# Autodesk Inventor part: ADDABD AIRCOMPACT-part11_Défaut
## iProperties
Shininess: 64.0
Length Units: 11269
Angle Units: 11279
Time Units: 11290
Mass Units: 11283
Length Display Precision: 3
Angle Display Precision: 2
Compacted: True
Part Number: ADDABD AIRCOMPACT-part11_Défaut
Document SubType Name: Modeling
Created: 2006-01
Material: Par défaut
Designer: riri
Density: 0.0
Volumn: 0.0
Area: 0.0
PropertySet Name: Model Information
Control State: 0
Master: False
Checked Out: False
Author: riri
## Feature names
1. Base1
